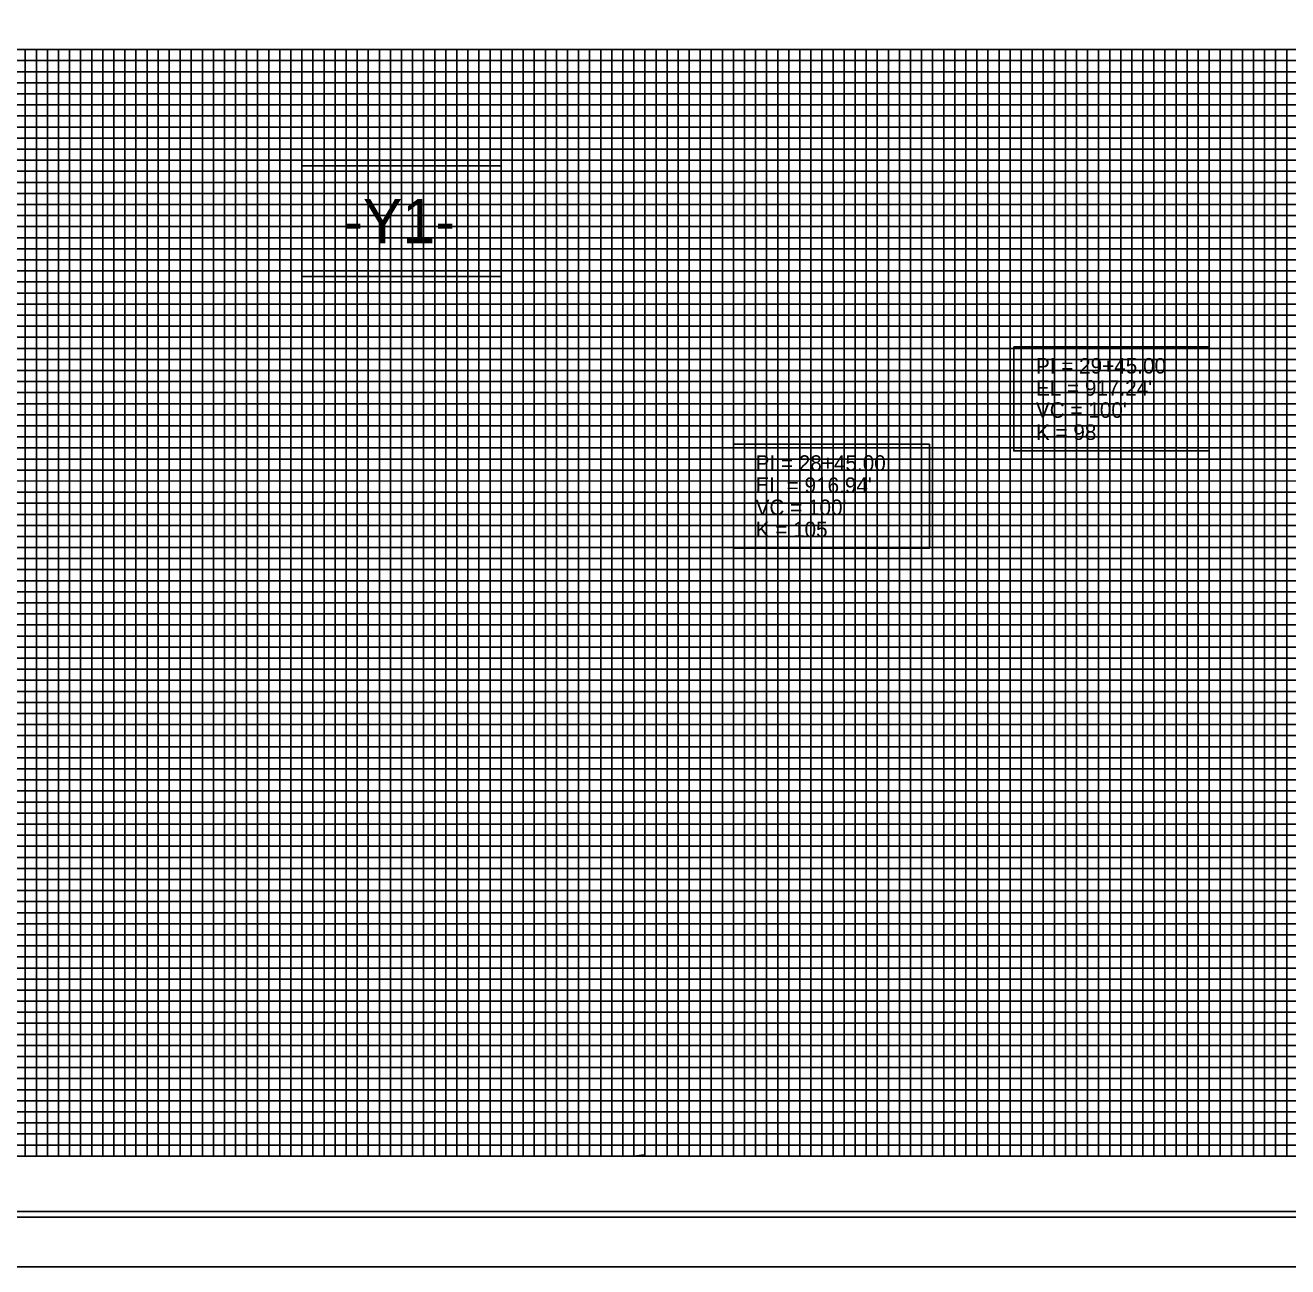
# Model space of a CAD drawing. Extents: x 1648157 to 1650776, y 832691 to 834781.
# Drawn here: x 1649609 to 1650180, y 832691 to 833252 of the extents above; entities that cross this region are included whole.
import ezdxf

# ---------------------------------------------------------------- set-up
doc = ezdxf.new("R2010")
doc.units = 0
for name, color, linetype in [('Exist Vertical Profile Horizontal Axis Label Major', 7, 'Continuous'), ('Prop Grid Mask', 7, 'Continuous'), ('Prop Vertical Profile Curve Label', 7, 'Continuous'), ('Prop VPI Label', 7, 'Continuous'), ('Sheet Cutting Line CELL', 7, 'Continuous'), ('Sheet DOT Grid CELL', 7, 'Continuous'), ('Sheet Layout Profile Border Port 2', 7, 'Continuous'), ('Sheet Plot Border Inside CELL', 7, 'Continuous'), ('Sheet Plot Border Outside CELL', 7, 'Continuous'), ('Sheet Profile CELL', 7, 'Continuous'), ('Sheet Profile Grid Major CELL', 7, 'Continuous'), ('Sheet Profile Grid Middle CELL', 7, 'Continuous'), ('Sheet Profile Grid Minor CELL', 7, 'Continuous')]:
    doc.layers.add(name, color=color, linetype=linetype)

msp = doc.modelspace()

# ---------------------------------------------------------------- linework, layer by layer
at = {"layer": 'Prop Grid Mask'}
for points in [[(1649734.28, 833188.52), (1649734.28, 833138.52), (1649824.28, 833138.52), (1649824.28, 833188.52)], [(1650055.95, 833106.64), (1650055.95, 833059.64), (1650144.28, 833059.64), (1650144.28, 833106.64)], [(1649929.28, 833062.7), (1649929.28, 833015.7), (1650017.84, 833015.7), (1650017.84, 833062.7)]]:
    msp.add_lwpolyline(points, close=True, dxfattribs=at)
at = {"layer": 'Sheet Cutting Line CELL'}
msp.add_line((1648862.28, 832691.02), (1650546.28, 832691.02), dxfattribs=at)
at = {"layer": 'Sheet DOT Grid CELL'}
for p, q in [((1649029.28, 833241.02), (1650529.17, 833241.02)), ((1649629.28, 833241.02), (1649629.28, 832741.02)), ((1649679.28, 833241.02), (1649679.28, 832741.02)), ((1649729.28, 833241.02), (1649729.28, 832741.02)), ((1649779.28, 833241.02), (1649779.28, 832741.02)), ((1649829.28, 833241.02), (1649829.28, 832741.02)), ((1649879.28, 833241.02), (1649879.28, 832741.02)), ((1649929.28, 833241.02), (1649929.28, 832741.02)), ((1649979.28, 833241.02), (1649979.28, 832741.02)), ((1650029.28, 833241.02), (1650029.28, 832741.02)), ((1650079.28, 833241.02), (1650079.28, 832741.02)), ((1650129.28, 833241.02), (1650129.28, 832741.02)), ((1650179.28, 833241.02), (1650179.28, 832741.02)), ((1649029.28, 833191.02), (1650529.17, 833191.02)), ((1649029.28, 833141.02), (1650529.17, 833141.02)), ((1649029.28, 833091.02), (1650529.17, 833091.02)), ((1649029.28, 833041.02), (1650529.17, 833041.02)), ((1649029.28, 832991.02), (1650529.17, 832991.02)), ((1649029.28, 832941.02), (1650529.17, 832941.02)), ((1649029.28, 832891.02), (1650529.17, 832891.02)), ((1649029.28, 832841.02), (1650529.17, 832841.02)), ((1649029.28, 832791.02), (1650529.17, 832791.02))]:
    msp.add_line(p, q, dxfattribs=at)
at = {"layer": 'Sheet Layout Profile Border Port 2'}
msp.add_lwpolyline([(1649079.28, 833241.02), (1650479.28, 833241.02), (1650479.28, 832741.02), (1649079.28, 832741.02)], close=True, dxfattribs=at)
at = {"layer": 'Sheet Plot Border Inside CELL'}
msp.add_lwpolyline([(1648875.28, 832713.47), (1650541.78, 832713.47), (1650541.78, 833768.57), (1648875.28, 833768.57)], close=True, dxfattribs=at)
at = {"layer": 'Sheet Plot Border Outside CELL'}
msp.add_lwpolyline([(1648862.28, 832691.02), (1650546.28, 832691.02), (1650546.28, 833791.02), (1648862.28, 833791.02)], close=True, dxfattribs=at)
at = {"layer": 'Sheet Profile CELL'}
for p, q in [((1649029.28, 833241.02), (1650529.28, 833241.02)), ((1650529.28, 832741.02), (1649029.28, 832741.02)), ((1649029.28, 832716.02), (1650529.28, 832716.02))]:
    msp.add_line(p, q, dxfattribs=at)
msp.add_lwpolyline([(1650529.28, 833766.02), (1649029.28, 833766.02), (1649029.28, 832716.02), (1650529.28, 832716.02)], close=True, dxfattribs=at)
at = {"layer": 'Sheet Profile Grid Major CELL'}
for p, q in [((1649629.28, 833241.02), (1649679.28, 833241.02)), ((1649729.28, 833241.02), (1649779.28, 833241.02)), ((1649829.28, 833241.02), (1649879.28, 833241.02)), ((1649929.28, 833241.02), (1649979.28, 833241.02)), ((1650029.28, 833241.02), (1650079.28, 833241.02)), ((1650129.28, 833241.02), (1650179.28, 833241.02))]:
    msp.add_line(p, q, dxfattribs=at)
for points in [[(1649579.28, 832741.02), (1649629.28, 832741.02), (1649629.28, 833241.02), (1649679.28, 833241.02), (1649679.28, 832741.02), (1649729.28, 832741.02), (1649729.28, 833241.02), (1649779.28, 833241.02), (1649779.28, 832741.02), (1649829.28, 832741.02), (1649829.28, 833241.02), (1649879.28, 833241.02), (1649879.28, 832741.02), (1649929.28, 832741.02), (1649929.28, 833241.02), (1649979.28, 833241.02), (1649979.28, 832741.02), (1650029.28, 832741.02), (1650029.28, 833241.02), (1650079.28, 833241.02), (1650079.28, 832741.02), (1650129.28, 832741.02), (1650129.28, 833241.02), (1650179.28, 833241.02), (1650179.28, 832741.02), (1650229.28, 832741.02)], [(1650529.28, 833191.02), (1649029.28, 833191.02)], [(1650529.28, 833141.02), (1649029.28, 833141.02), (1649029.28, 833091.02), (1650529.28, 833091.02)], [(1650529.28, 833041.02), (1649029.28, 833041.02), (1649029.28, 832991.02), (1650529.28, 832991.02)], [(1650529.28, 832941.02), (1649029.28, 832941.02), (1649029.28, 832891.02), (1650529.28, 832891.02)], [(1650529.28, 832841.02), (1649029.28, 832841.02), (1649029.28, 832841.02), (1649029.28, 832791.02), (1650529.28, 832791.02)], [(1650529.28, 832741.02), (1649029.28, 832741.02)]]:
    msp.add_lwpolyline(points, dxfattribs=at)
at = {"layer": 'Sheet Profile Grid Middle CELL'}
for points in [[(1649604.28, 832741.02), (1649654.28, 832741.02), (1649654.28, 832741.02), (1649654.28, 833241.02), (1649704.28, 833241.02), (1649704.28, 832741.02), (1649754.28, 832741.02), (1649754.28, 833241.02), (1649804.28, 833241.02), (1649804.28, 832741.02), (1649854.28, 832741.02), (1649854.28, 833241.02), (1649904.28, 833241.02), (1649904.28, 832741.02), (1649954.28, 832741.02), (1649954.28, 833241.02), (1650004.28, 833241.02), (1650004.28, 832741.02), (1650054.28, 832741.02), (1650054.28, 833241.02), (1650104.28, 833241.02), (1650104.28, 832741.02), (1650154.28, 832741.02), (1650154.28, 833241.02), (1650204.28, 833241.02)], [(1649029.28, 833216.02), (1650529.28, 833216.02)], [(1650529.28, 833166.02), (1649029.28, 833166.02), (1649029.28, 833116.02), (1650529.28, 833116.02)], [(1650529.28, 833066.02), (1649029.28, 833066.02), (1649029.28, 833016.02), (1650529.28, 833016.02)], [(1650529.28, 832966.02), (1649029.28, 832966.02), (1649029.28, 832916.02), (1650529.28, 832916.02)], [(1650529.28, 832866.02), (1649029.28, 832866.02), (1649029.28, 832816.02), (1650529.28, 832816.02)], [(1650529.28, 832766.02), (1649029.28, 832766.02)]]:
    msp.add_lwpolyline(points, dxfattribs=at)
at = {"layer": 'Sheet Profile Grid Minor CELL'}
for p, q in [((1649079.28, 833236.02), (1650479.28, 833236.02)), ((1650479.28, 833231.02), (1649079.28, 833231.02)), ((1649079.28, 833226.02), (1650479.28, 833226.02)), ((1650479.28, 833221.02), (1649079.28, 833221.02)), ((1649079.28, 833211.02), (1650479.28, 833211.02)), ((1650479.28, 833206.02), (1649079.28, 833206.02)), ((1649079.28, 833201.02), (1650479.28, 833201.02)), ((1650479.28, 833196.02), (1649079.28, 833196.02)), ((1649079.28, 833186.02), (1650479.28, 833186.02)), ((1650479.28, 833181.02), (1649079.28, 833181.02)), ((1649079.28, 833176.02), (1650479.28, 833176.02)), ((1650479.28, 833171.02), (1649079.28, 833171.02)), ((1649079.28, 833161.02), (1650479.28, 833161.02)), ((1650479.28, 833156.02), (1649079.28, 833156.02)), ((1649079.28, 833151.02), (1650479.28, 833151.02)), ((1650479.28, 833146.02), (1649079.28, 833146.02)), ((1649079.28, 833136.02), (1650479.28, 833136.02)), ((1650479.28, 833131.02), (1649079.28, 833131.02)), ((1649079.28, 833126.02), (1650479.28, 833126.02)), ((1650479.28, 833121.02), (1649079.28, 833121.02)), ((1649079.28, 833111.02), (1650479.28, 833111.02)), ((1650479.28, 833106.02), (1649079.28, 833106.02)), ((1649079.28, 833101.02), (1650479.28, 833101.02)), ((1650479.28, 833096.02), (1649079.28, 833096.02)), ((1649079.28, 833086.02), (1650479.28, 833086.02)), ((1650479.28, 833081.02), (1649079.28, 833081.02)), ((1649079.28, 833076.02), (1650479.28, 833076.02)), ((1650479.28, 833071.02), (1649079.28, 833071.02)), ((1649079.28, 833061.02), (1650479.28, 833061.02)), ((1650479.28, 833056.02), (1649079.28, 833056.02)), ((1649079.28, 833051.02), (1650479.28, 833051.02)), ((1650479.28, 833046.02), (1649079.28, 833046.17)), ((1649079.28, 833036.02), (1650479.28, 833036.02)), ((1650479.28, 833031.02), (1649079.28, 833031.02)), ((1649079.28, 833026.02), (1650479.28, 833026.02)), ((1650479.28, 833021.02), (1649079.28, 833021.02)), ((1649079.28, 833011.02), (1650479.28, 833011.02)), ((1650479.28, 833006.02), (1649079.28, 833006.02)), ((1649079.28, 833001.02), (1650479.28, 833001.02)), ((1650479.28, 832996.02), (1649079.28, 832996.02)), ((1649079.28, 832986.02), (1650479.28, 832986.02)), ((1650479.28, 832981.02), (1649079.28, 832981.02)), ((1649079.28, 832976.02), (1650479.28, 832976.02)), ((1650479.28, 832971.02), (1649079.28, 832971.02)), ((1649079.28, 832961.02), (1650479.28, 832961.02)), ((1650479.28, 832956.02), (1649079.28, 832956.02)), ((1649079.28, 832951.02), (1650479.28, 832951.02)), ((1650479.28, 832946.02), (1649079.28, 832946.02)), ((1649079.28, 832936.02), (1650479.28, 832936.02)), ((1650479.28, 832931.02), (1649079.28, 832931.02)), ((1649079.28, 832926.02), (1650479.28, 832926.02)), ((1650479.28, 832921.02), (1649079.28, 832921.02)), ((1649079.28, 832911.02), (1650479.28, 832911.02)), ((1650479.28, 832906.02), (1649079.28, 832906.02)), ((1649079.28, 832901.02), (1650479.28, 832901.02)), ((1650479.28, 832896.02), (1649079.28, 832896.02)), ((1649079.28, 832886.02), (1650479.28, 832886.02)), ((1650479.28, 832881.02), (1649079.28, 832881.02)), ((1649079.28, 832876.02), (1650479.28, 832876.02)), ((1650479.28, 832871.02), (1649079.28, 832871.02)), ((1649079.28, 832861.02), (1650479.28, 832861.02)), ((1650479.28, 832856.02), (1649079.28, 832856.02)), ((1649079.28, 832851.02), (1650479.28, 832851.02)), ((1650479.28, 832846.02), (1649079.28, 832846.02)), ((1649079.28, 832836.02), (1650479.28, 832836.02)), ((1650479.28, 832831.02), (1649079.28, 832831.02)), ((1649079.28, 832826.02), (1650479.28, 832826.02)), ((1650479.28, 832821.02), (1649079.28, 832821.02)), ((1649079.28, 832811.02), (1650479.28, 832811.02)), ((1650479.28, 832806.02), (1649079.28, 832806.02)), ((1649079.28, 832801.02), (1650479.28, 832801.02)), ((1650479.28, 832796.02), (1649079.28, 832796.02)), ((1649079.28, 832786.02), (1650479.28, 832786.02)), ((1650479.28, 832781.02), (1649079.28, 832781.02)), ((1649079.28, 832776.02), (1650479.28, 832776.02)), ((1650479.28, 832771.02), (1649079.28, 832771.02)), ((1649079.28, 832761.02), (1650479.28, 832761.02)), ((1650479.28, 832756.02), (1649079.28, 832756.02)), ((1649079.28, 832751.02), (1650479.28, 832751.02)), ((1649079.28, 832746.02), (1650479.28, 832746.02))]:
    msp.add_line(p, q, dxfattribs=at)
for points in [[(1649599.28, 833241.02), (1649609.28, 833241.02)], [(1649609.28, 833241.02), (1649609.28, 832741.02), (1649614.28, 832741.02), (1649614.28, 833241.02), (1649619.28, 833241.02), (1649619.28, 832741.02), (1649624.28, 832741.02), (1649624.28, 833241.02), (1649634.28, 833241.02), (1649634.28, 832741.02), (1649639.28, 832741.02), (1649639.28, 833241.02), (1649644.28, 833241.02), (1649644.28, 832741.02), (1649649.28, 832741.02), (1649649.28, 833241.02), (1649659.28, 833241.02), (1649659.28, 832741.02), (1649664.28, 832741.02), (1649664.28, 833241.02), (1649669.28, 833241.02), (1649669.28, 832741.02), (1649674.28, 832741.02), (1649674.28, 833241.02), (1649684.28, 833241.02), (1649684.28, 832741.02), (1649689.28, 832741.02), (1649689.28, 833241.02), (1649694.28, 833241.02), (1649694.28, 832741.02), (1649699.28, 832741.02), (1649699.28, 833241.02), (1649709.28, 833241.02), (1649709.28, 832741.02), (1649714.28, 832741.02), (1649714.28, 833241.02), (1649719.28, 833241.02), (1649719.28, 832741.02), (1649724.28, 832741.02), (1649724.28, 833241.02), (1649734.28, 833241.02), (1649734.28, 832741.02), (1649734.28, 832741.02), (1649739.28, 832741.02), (1649739.28, 833241.02), (1649744.28, 833241.02), (1649744.28, 832741.02), (1649749.28, 832741.02), (1649749.28, 833241.02), (1649759.28, 833241.02), (1649759.28, 832741.02), (1649764.28, 832741.02), (1649764.28, 833241.02), (1649769.28, 833241.02), (1649769.28, 832741.02), (1649774.28, 832741.02), (1649774.28, 833241.02), (1649784.28, 833241.02), (1649784.28, 832741.02), (1649789.28, 832741.02), (1649789.28, 833241.02), (1649794.28, 833241.02), (1649794.28, 832741.02), (1649799.28, 832741.02), (1649799.28, 833241.02), (1649809.28, 833241.02), (1649809.28, 832741.02), (1649814.28, 832741.02), (1649814.28, 833241.02), (1649819.28, 833241.02), (1649819.28, 832741.02), (1649824.28, 832741.02), (1649824.28, 833241.02), (1649834.28, 833241.02), (1649834.28, 832741.02), (1649839.28, 832741.02), (1649839.28, 833241.02), (1649844.28, 833241.02), (1649844.28, 832741.02), (1649849.28, 832741.02), (1649849.28, 833241.02), (1649859.28, 833241.02), (1649859.28, 832741.02), (1649864.28, 832741.02), (1649864.28, 833241.02), (1649869.28, 833241.02), (1649869.28, 832741.02), (1649874.28, 832741.02), (1649874.28, 833241.02), (1649884.28, 833241.02), (1649884.28, 832741.02), (1649888.98, 832741.57), (1649889.28, 832741.02), (1649889.28, 833241.02), (1649894.28, 833241.02), (1649894.28, 832741.02), (1649899.28, 832741.02), (1649899.28, 833241.02), (1649909.28, 833241.02), (1649909.28, 832741.02), (1649914.28, 832741.02)], [(1649914.28, 832741.02), (1649914.28, 833241.02), (1649919.28, 833241.02), (1649919.28, 832741.02), (1649924.28, 832741.02), (1649924.28, 833241.02), (1649934.28, 833241.02), (1649934.28, 832741.02), (1649939.28, 832741.02), (1649939.28, 833241.02), (1649944.28, 833241.02), (1649944.28, 832741.02), (1649949.28, 832741.02), (1649949.28, 833241.02), (1649959.28, 833241.02), (1649959.28, 832741.02), (1649964.28, 832741.02), (1649964.28, 833241.02), (1649969.28, 833241.02), (1649969.28, 832741.02), (1649974.28, 832741.02), (1649974.28, 833241.02), (1649984.28, 833241.02), (1649984.28, 832741.02), (1649989.28, 832741.02), (1649989.28, 833241.02), (1649994.28, 833241.02), (1649994.28, 832741.02), (1649999.28, 832741.02), (1649999.28, 833241.02), (1650009.28, 833241.02), (1650009.28, 832741.02), (1650014.28, 832741.02), (1650014.28, 833241.02), (1650019.28, 833241.02), (1650019.28, 832741.02), (1650024.28, 832741.02), (1650024.28, 833241.02), (1650034.28, 833241.02), (1650034.28, 832741.02), (1650039.28, 832741.02), (1650039.28, 833241.02), (1650044.28, 833241.02), (1650044.28, 832741.02), (1650049.28, 832741.02), (1650049.28, 833241.02), (1650059.28, 833241.02), (1650059.28, 832741.02), (1650064.28, 832741.02), (1650064.28, 833241.02), (1650069.28, 833241.02), (1650069.28, 832741.02), (1650074.28, 832741.02), (1650074.28, 833241.02), (1650084.28, 833241.02), (1650084.28, 832741.02), (1650089.28, 832741.02), (1650089.28, 833241.02), (1650094.28, 833241.02), (1650094.28, 832741.02), (1650099.28, 832741.02), (1650099.28, 833241.02), (1650109.28, 833241.02), (1650109.28, 832741.02), (1650114.28, 832741.02), (1650114.28, 833241.02), (1650119.28, 833241.02), (1650119.28, 832741.02), (1650124.28, 832741.02), (1650124.28, 833241.02), (1650134.28, 833241.02), (1650134.28, 832741.02), (1650139.28, 832741.02), (1650139.28, 833241.02), (1650144.28, 833241.02), (1650144.28, 832741.02), (1650149.28, 832741.02), (1650149.28, 833241.02), (1650159.28, 833241.02), (1650159.28, 832741.02), (1650164.28, 832741.02), (1650164.28, 833241.02), (1650169.28, 833241.02), (1650169.28, 832741.02), (1650174.28, 832741.02), (1650174.28, 833241.02), (1650184.28, 833241.02)]]:
    msp.add_lwpolyline(points, dxfattribs=at)

# ---------------------------------------------------------------- texts
at = {"layer": 'Exist Vertical Profile Horizontal Axis Label Major'}
msp.add_text('-Y1-', height=20, dxfattribs=at).set_placement((1649752.92, 833153.52))
at = {"layer": 'Prop Vertical Profile Curve Label'}
for s, p in [("VC = 100'", (1650065.95, 833074.64)), ('K = 98', (1650065.95, 833064.64)), ("VC = 100'", (1649939.28, 833030.7)), ('K = 105', (1649939.28, 833020.7))]:
    msp.add_text(s, height=7, dxfattribs=at).set_placement(p)
at = {"layer": 'Prop VPI Label'}
for s, p in [('PI = 29+45.00', (1650065.95, 833094.64)), ("EL = 917.24'", (1650065.95, 833084.64)), ('PI = 28+45.00', (1649939.28, 833050.7)), ("EL = 916.94'", (1649939.28, 833040.7))]:
    msp.add_text(s, height=7, dxfattribs=at).set_placement(p)

doc.saveas('drawing.dxf')
